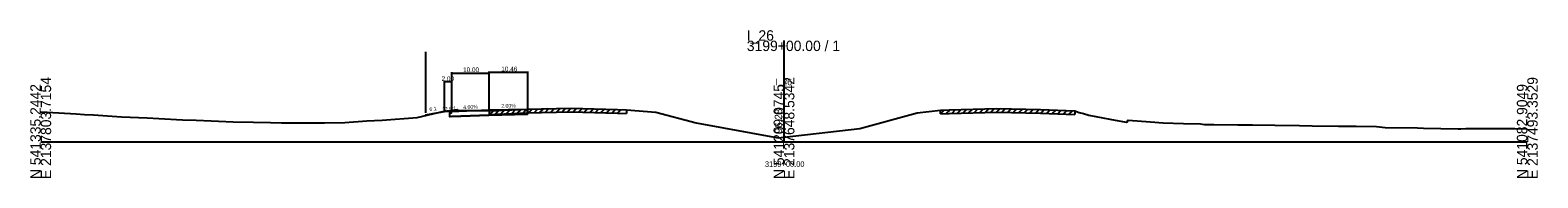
# Model space of a CAD drawing. Extents: x -13101 to 4803, y -924 to 22390.
# Drawn here: x 997.2 to 1402.8, y 19490.3 to 19530.1 of the extents above; entities that cross this region are included whole.
import ezdxf

# ---------------------------------------------------------------- set-up
doc = ezdxf.new("R2010")
doc.units = 0
for name, color, linetype in [('RD_GPK_XS_Cell', 7, 'Continuous'), ('RD_XD_TX_Width', 7, 'Continuous'), ('RD_XS_Base', 7, 'Continuous'), ('RD_XS_EarthShd', 7, 'Continuous'), ('RD_XS_EwShp', 7, 'Continuous'), ('RD_XS_ExGround', 7, 'Continuous'), ('RD_XS_ExPaveRet', 7, 'Continuous'), ('RD_XS_OSBase', 7, 'Continuous'), ('RD_XS_Pave', 7, 'Continuous'), ('RD_XS_TieSlope', 7, 'Continuous'), ('RD_XS_TX_Baseline', 7, 'Continuous'), ('RD_XS_TX_Elev_EX', 7, 'Continuous'), ('RD_XS_TX_ShdSlope', 7, 'Continuous'), ('RD_XS_TX_Slope', 7, 'Continuous'), ('RD_XS_TX_Station', 7, 'Continuous')]:
    doc.layers.add(name, color=color, linetype=linetype)

msp = doc.modelspace()

# ---------------------------------------------------------------- linework, layer by layer
at = {"layer": 'RD_GPK_XS_Cell'}
for p, q in [((1200, 19500), (1200, 19527.3)), ((1000, 19500), (1200, 19500)), ((1200, 19500), (1400, 19500))]:
    msp.add_line(p, q, dxfattribs=at)
at = {"layer": 'RD_XD_TX_Width'}
for p, q in [((1103.54, 19524.26), (1103.54, 19507.87)), ((1110.54, 19518.78), (1110.54, 19508.43)), ((1110.54, 19518.58), (1120.54, 19518.58)), ((1120.54, 19518.99), (1120.54, 19508.83)), ((1120.54, 19518.79), (1131, 19518.79)), ((1120.54, 19518.78), (1120.54, 19508.83)), ((1131, 19518.99), (1131, 19509.04)), ((1108.54, 19516.38), (1108.54, 19508.27)), ((1110.54, 19516.18), (1108.54, 19516.18)), ((1110.54, 19516.38), (1110.54, 19508.43))]:
    msp.add_line(p, q, dxfattribs=at)
at = {"layer": 'RD_XS_Base'}
for p, q in [((1110.54, 19506.83), (1120.54, 19507.23)), ((1120.54, 19507.23), (1131, 19507.44))]:
    msp.add_line(p, q, dxfattribs=at)
at = {"layer": 'RD_XS_EarthShd'}
msp.add_line((1110.54, 19508.23), (1108.54, 19508.07), dxfattribs=at)
at = {"layer": 'RD_XS_EwShp'}
for points in [[(1105.43, 19507.55), (1103.54, 19507.23), (1103.54, 19507.1)], [(1110.54, 19506.83), (1110.04, 19506.81), (1110.04, 19507.81), (1110.54, 19507.83), (1110.54, 19508.23), (1108.54, 19508.07), (1105.43, 19507.55), (1108.55, 19508.3), (1112.02, 19508.73), (1112.18, 19508.46), (1119.14, 19508.44), (1120.74, 19508.37), (1130.78, 19508.83), (1131, 19508.84), (1131, 19508.44), (1131, 19507.44), (1120.54, 19507.23)]]:
    msp.add_lwpolyline(points, close=True, dxfattribs=at)
at = {"layer": 'RD_XS_ExGround'}
msp.add_lwpolyline([(1000, 19508.13), (1001.76, 19508.02), (1009.58, 19507.53), (1011.77, 19507.41), (1014.22, 19507.29), (1021.78, 19506.81), (1028.62, 19506.51), (1031.79, 19506.34), (1038.18, 19505.95), (1041.8, 19505.83), (1045.88, 19505.7), (1051.81, 19505.44), (1057.27, 19505.31), (1061.82, 19505.2), (1064.75, 19505.18), (1066.69, 19505.17), (1071.83, 19505.12), (1076.39, 19505.16), (1081.84, 19505.27), (1087.77, 19505.66), (1091.85, 19505.87), (1101.26, 19506.55), (1108.55, 19508.3), (1112.02, 19508.73), (1112.18, 19508.46), (1119.14, 19508.44), (1120.74, 19508.37), (1130.78, 19508.83), (1142.76, 19509.1), (1155.21, 19508.78), (1157.58, 19508.67), (1165.48, 19508.03), (1176.36, 19505.13), (1198.41, 19501.11), (1200, 19501.28), (1220.37, 19503.58), (1235.79, 19507.87), (1242.15, 19508.59), (1244.48, 19508.67), (1257.3, 19509.04), (1269.06, 19508.75), (1278.23, 19508.39), (1279.38, 19507.95), (1280.59, 19507.62), (1282.03, 19507.18), (1287.63, 19506.16), (1292.04, 19505.37), (1292.35, 19505.45), (1292.61, 19505.87), (1298.58, 19505.4), (1302.05, 19505.13), (1307.48, 19504.96), (1312.06, 19504.84), (1312.58, 19504.79), (1313.13, 19504.73), (1315.66, 19504.7), (1322.07, 19504.62), (1326.07, 19504.57), (1332.08, 19504.5), (1338.73, 19504.41), (1342.09, 19504.38), (1349.23, 19504.28), (1352.1, 19504.27), (1353.92, 19504.23), (1359.43, 19504.18), (1361.78, 19503.91), (1370.45, 19503.76), (1372.11, 19503.72), (1381.44, 19503.57), (1382.12, 19503.56), (1383.42, 19503.58), (1396.69, 19503.63), (1400, 19503.53)], dxfattribs=at)
at = {"layer": 'RD_XS_ExPaveRet'}
for p, q in [((1120.74, 19507.37), (1121.79, 19508.42)), ((1120.74, 19507.37), (1120.74, 19508.37)), ((1120.74, 19507.37), (1130.78, 19507.83)), ((1122.24, 19507.44), (1123.29, 19508.49)), ((1123.74, 19507.51), (1124.79, 19508.56)), ((1125.24, 19507.58), (1126.29, 19508.63)), ((1126.74, 19507.65), (1127.79, 19508.7)), ((1128.24, 19507.72), (1129.29, 19508.76)), ((1129.74, 19507.79), (1130.79, 19508.83)), ((1130.78, 19507.83), (1142.76, 19508.1)), ((1131.24, 19507.84), (1132.26, 19508.87)), ((1132.74, 19507.88), (1133.76, 19508.9)), ((1134.24, 19507.91), (1135.26, 19508.93)), ((1135.74, 19507.94), (1136.76, 19508.97)), ((1137.24, 19507.98), (1138.26, 19509)), ((1138.74, 19508.01), (1139.76, 19509.03)), ((1140.24, 19508.04), (1141.26, 19509.07)), ((1141.74, 19508.08), (1142.76, 19509.1)), ((1142.76, 19508.1), (1155.21, 19507.78)), ((1143.24, 19508.09), (1144.22, 19509.06)), ((1144.74, 19508.05), (1145.72, 19509.02)), ((1146.24, 19508.01), (1147.22, 19508.99)), ((1147.74, 19507.97), (1148.72, 19508.95)), ((1149.24, 19507.93), (1150.22, 19508.91)), ((1150.74, 19507.9), (1151.72, 19508.87)), ((1152.24, 19507.86), (1153.22, 19508.83)), ((1153.74, 19507.82), (1154.72, 19508.79)), ((1155.21, 19507.78), (1157.58, 19507.67)), ((1155.24, 19507.78), (1156.2, 19508.74)), ((1157.58, 19508.67), (1157.58, 19507.67)), ((1242.15, 19507.59), (1243.18, 19508.63)), ((1242.15, 19507.59), (1242.15, 19508.59)), ((1242.15, 19507.59), (1244.48, 19507.67)), ((1243.65, 19507.64), (1244.68, 19508.67)), ((1244.48, 19507.67), (1257.3, 19508.04)), ((1245.15, 19507.69), (1246.18, 19508.72)), ((1246.65, 19507.73), (1247.68, 19508.76)), ((1248.15, 19507.78), (1249.18, 19508.81)), ((1249.65, 19507.82), (1250.68, 19508.85)), ((1251.15, 19507.86), (1252.18, 19508.89)), ((1252.65, 19507.91), (1253.68, 19508.94)), ((1254.15, 19507.95), (1255.18, 19508.98)), ((1255.65, 19508), (1256.68, 19509.03)), ((1257.15, 19508.04), (1258.14, 19509.02)), ((1257.3, 19508.04), (1269.06, 19507.75)), ((1258.65, 19508.01), (1259.63, 19508.99)), ((1260.15, 19507.97), (1261.13, 19508.95)), ((1261.65, 19507.94), (1262.63, 19508.91)), ((1263.15, 19507.9), (1264.13, 19508.87)), ((1264.65, 19507.86), (1265.63, 19508.84)), ((1266.15, 19507.82), (1267.13, 19508.8)), ((1267.65, 19507.78), (1268.63, 19508.76)), ((1269.06, 19507.75), (1278.23, 19507.39)), ((1269.15, 19507.75), (1270.11, 19508.71)), ((1270.65, 19507.69), (1271.61, 19508.65)), ((1272.15, 19507.63), (1273.11, 19508.59)), ((1273.65, 19507.57), (1274.61, 19508.53)), ((1275.15, 19507.51), (1276.11, 19508.47)), ((1276.65, 19507.45), (1277.61, 19508.42)), ((1278.23, 19508.39), (1278.23, 19507.39))]:
    msp.add_line(p, q, dxfattribs=at)
at = {"layer": 'RD_XS_OSBase'}
for p, q in [((1110.04, 19507.81), (1110.54, 19507.83)), ((1110.04, 19506.81), (1110.04, 19507.81)), ((1110.54, 19506.83), (1110.04, 19506.81)), ((1110.54, 19507.83), (1110.54, 19508.23)), ((1131, 19508.44), (1131, 19508.84)), ((1131, 19507.44), (1131, 19508.44))]:
    msp.add_line(p, q, dxfattribs=at)
at = {"layer": 'RD_XS_Pave'}
for p, q in [((1110.54, 19508.23), (1120.54, 19508.63)), ((1120.54, 19508.63), (1131, 19508.84))]:
    msp.add_line(p, q, dxfattribs=at)
at = {"layer": 'RD_XS_TieSlope'}
for p, q in [((1108.54, 19508.07), (1103.54, 19507.23)), ((1103.54, 19507.23), (1103.54, 19507.1))]:
    msp.add_line(p, q, dxfattribs=at)

# ---------------------------------------------------------------- texts
at = {"layer": 'RD_GPK_XS_Cell'}
for s, p in [('I_26', (1190, 19527.3)), ('3199+00.00 / 1', (1190, 19524.5))]:
    msp.add_text(s, height=2.8, dxfattribs=at).set_placement(p)
for s, p in [('E 2137803.7154', (1002.8, 19490)), ('N 541335.2442', (1000, 19490)), ('N 541209.0745', (1200, 19490)), ('E 2137648.5342', (1202.8, 19490)), ('N 541082.9049', (1400, 19490)), ('E 2137493.3529', (1402.8, 19490))]:
    msp.add_text(s, height=2.8, rotation=90, dxfattribs=at).set_placement(p)
at = {"layer": 'RD_XD_TX_Width'}
for s, p in [('2.00', (1107.85, 19516.43)), ('10.00', (1113.65, 19518.83)), ('10.46', (1123.92, 19519.04))]:
    msp.add_text(s, height=1.25, dxfattribs=at).set_placement(p)
at = {"layer": 'RD_XS_TX_Baseline'}
msp.add_text('I_26', height=1.75, dxfattribs=at).set_placement((1197.6, 19515.28))
at = {"layer": 'RD_XS_TX_Elev_EX'}
msp.add_text('96.28', height=2, rotation=90, dxfattribs=at).set_placement((1199.5, 19502.28))
at = {"layer": 'RD_XS_TX_ShdSlope'}
msp.add_text('12.5:1', height=1, rotation=4.5739, dxfattribs=at).set_placement((1108.01, 19508.28))
msp.add_text('12.5:1', height=1, rotation=4.5739, dxfattribs=at).set_placement((1108.01, 19508.28))
at = {"layer": 'RD_XS_TX_Slope'}
for s, rotation, p in [('6:1', 9.4623, (1104.68, 19508.26)), ('4.00%', 2.2906, (1113.72, 19508.86)), ('2.00%', 1.1458, (1123.92, 19509.2))]:
    msp.add_text(s, height=1, rotation=rotation, dxfattribs=at).set_placement(p)
at = {"layer": 'RD_XS_TX_Station'}
msp.add_text('3199+00.00', height=1.5, dxfattribs=at).set_placement((1194.86, 19493.28))

doc.saveas('drawing.dxf')
